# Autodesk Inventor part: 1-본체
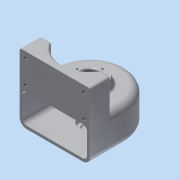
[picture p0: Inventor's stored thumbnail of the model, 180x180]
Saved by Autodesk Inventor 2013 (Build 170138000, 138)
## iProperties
Created: 2015-02
Part Number: 1-본체
Material: 알루미늄 6061
Document SubType Name: Modeling
Designer: Administrator
Density: 2.71 g/cm^3
Mass: 575.526 g
Surface Area: 706.56 cm^2
Volume: 212.371 cm^3
Author: Administrator
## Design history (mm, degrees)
sketch "스케치1" dims "d0" = 50
  geometry: L1 (50, 0)-(-50, 0); L2 (-50, 0)-(-50, -50); L3 (-50, -50)-(50, -50); L4 (50, -50)-(50, 0); 2 further points
  constraints: 8 end point, 2 parallel, 2 vertical, 1 coincident, 1 horizontal, 1 horizontal alignment, 1 perpendicular, 2 other
  dimensions: "d2" = 50 distance between parallel lines of L3 L1
extrude "돌출1" new body sketch "스케치1" distance "d3" = 50; taper "d4" = 0 deg
fillet "모깎기1" dims "d5" = 10
node "작업 평면1"
feature "쉘1" dims "d28" = 4
sketch "스케치2"
  geometry: L1 (-40, -50)-(40, -50) reference; L2 (-40, -50)-(-50, -50) reference; L3 (50, -50)-(40, -50) reference; L4 (50, -50)-(50, 0) reference; L5 (-50, 0)-(-50, -50) reference; L6 (-50, -20)-(-34.641, -20); L7 (-34.641, -20)-(34.641, -20); L8 (34.641, -20)-(50, -20); A1 r 40 centre (0, 0) between (-34.641, -20) and (34.641, -20); A2 r 40 centre (0, 0) between (34.641, -20) and (-34.641, -20); 1 further point
  constraints: 6 end point, 4 point on circle, 3 perpendicular, 2 centre point, 2 point on line, 1 coincident
  dimensions: "d7" = 40 radius of A1; "d9" = 30 distance between parallel lines of L1 L6
extrude "돌출2" join sketch "스케치2" stored distance "d10" = 50; taper "d11" = 0 deg
sketch "스케치3"
  geometry: C1 r 25 at (0, 0); A1 r 40 centre (0, 0) between (-34.641, -20) and (34.641, -20) reference
  constraints: 1 centre point, 1 coincident
  dimensions: "d12" = 50 diameter of C1
extrude "돌출3" join sketch "스케치3" distance "d14" = 10; taper "d15" = -20 deg
sketch "스케치4"
  geometry: C1 r 20 at (0, 1.303); A1 r 40 centre (0, 1.303) between (40, 1.303) and (-40, 1.303) reference
  constraints: 1 centre point, 1 coincident
  dimensions: "d16" = 40 diameter of C1
extrude "돌출4" join sketch "스케치4" taper "d18" = 0 deg; distance "d19" = 9
sketch "스케치5"
  geometry: C1 r 21.36 at (0, 0) reference; 1 further point
  constraints: 1 coincident
hole "구멍1" sketch "스케치5" at (0, 0) diameter "d21" = 20; stored, may be unused: countersink angle "d25" = 90 deg, drill point angle "d27" = 0 deg; dims "d22" = 6, "d23" = 28, "d24" = 10, "d26" = 14
sketch "스케치6"
  geometry: C1 r 21.36 at (0, 8.803); A1 r 40 centre (0, 8.803) between (40, 8.803) and (-40, 8.803) reference; 1 further point
  constraints: 2 coincident, 1 centre point
hole "구멍2" sketch "스케치6" at (0, 8.803) diameter "d35" = 20; stored, may be unused: drill point angle "d30" = 0 deg, countersink angle "d31" = 90 deg; dims "d29" = 6, "d32" = 8, "d33" = 28, "d34" = 10
chamfer "모따기1" distance "d36" = 1; stored, may be unused: second distance "d37" = 2, angle "d38" = 45 deg
fillet "모깎기2" dims "d39" = 0.3, "d40" = 3
sketch "스케치7"
  geometry: C1 r 21.36 at (0, 0) reference; 4 further points
  constraints: 1 vertical alignment, 5 other
  dimensions: "d43" = 360 deg dimension on C1.centre point (0, 18) (derived); "d45" = 36 distance of point (0, -18) point (0, 18)
hole "구멍3" sketch "스케치7" at (0, 18), (-18, 0), (0, -18), (18, 0) diameter "d46" = 2.459; stored, may be unused: countersink angle "d50" = 90 deg, drill point angle "d52" = 118 deg; dims "d47" = 6, "d48" = 28, "d49" = 10, "d51" = 9
sketch "스케치8"
  geometry: L1 (-7, 95)-(87, 95) reference; L2 (81.75, 86)-(-1.75, 86); L3 (-1.75, 86)-(-1.75, 53); L4 (-1.75, 53)-(81.75, 53); L5 (81.75, 53)-(81.75, 86); 7 further points
  constraints: 8 end point, 4 coincident, 2 midpoint, 2 parallel, 1 horizontal, 1 perpendicular, 1 vertical alignment
  dimensions: "d53" = 33 distance of L4.end L2.start; "d55" = 83.5 distance of L2.start L2.end; "d56" = 9 distance between parallel lines of L1 L2
hole "구멍4" sketch "스케치8" at (81.75, 86), (81.75, 53), (-1.75, 86), (-1.75, 53) diameter "d57" = 5.134; stored, may be unused: countersink angle "d61" = 90 deg, drill point angle "d63" = 118 deg; dims "d58" = 10, "d59" = 28, "d60" = 10, "d62" = 13
node "작업 평면2"
sketch "스케치9"
  geometry: L1 (40, 0)-(-40, 0) reference; 2 further points
  constraints: 1 vertical alignment, 1 other
  dimensions: "d65" = 25 distance from line of L1 point (0, 25)
feature "엠보싱1" sketch "스케치9" dims "d0" = 50, "d2" = 50, "d9" = 30, "d66" = 0.5, "d67" = 0
node "솔리드1"
other parameters: "d6" = -95, "d64" = 76
